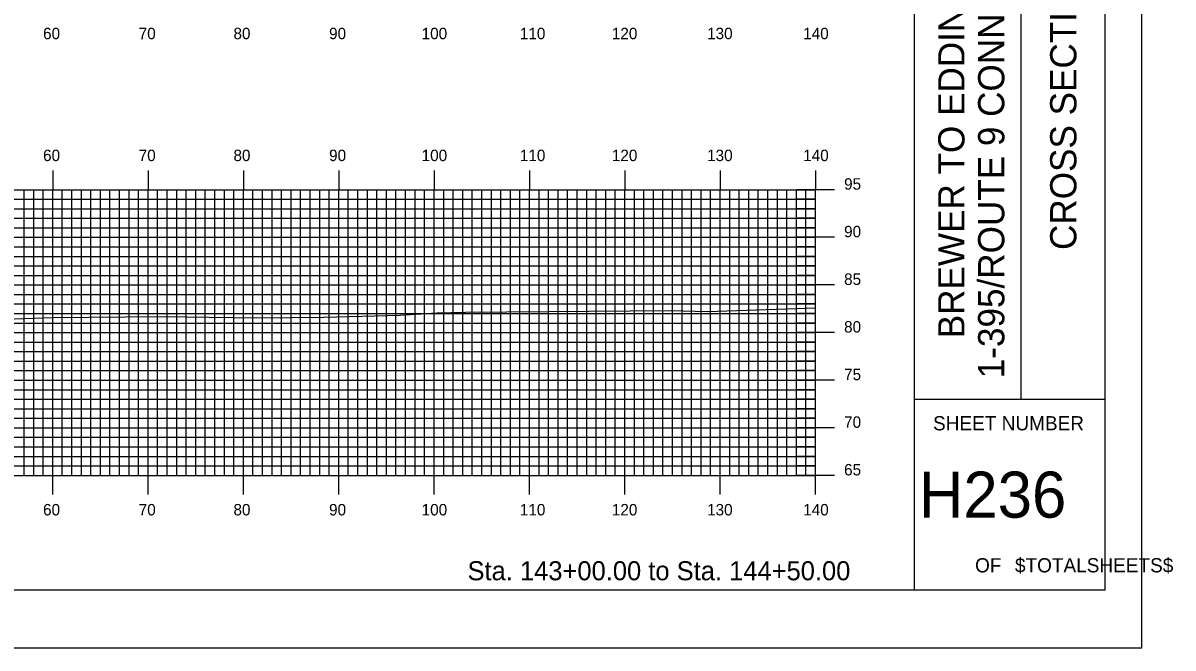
# Model space of a CAD drawing. Extents: x 1777138 to 1777481, y 442591 to 442811.
# Drawn here: x 1777360.6 to 1777481.3, y 442590.5 to 442656.2 of the extents above; entities that cross this region are included whole.
import ezdxf

# ---------------------------------------------------------------- set-up
doc = ezdxf.new("R2010")
doc.units = 0
for name, color, linetype in [('BORDER', 7, 'Continuous'), ('H_V ANNOTATION', 7, 'Continuous'), ('MAJOR', 7, 'Continuous'), ('MINOR', 7, 'Continuous'), ('PLOT BOUNDARY', 7, 'Continuous'), ('S_Roadway_Centerline', 7, 'Continuous')]:
    doc.layers.add(name, color=color, linetype=linetype)

msp = doc.modelspace()

# ---------------------------------------------------------------- linework, layer by layer
at = {"layer": 'BORDER'}
for p, q in [((1777454.16, 442596.67), (1777454.16, 442806.67)), ((1777465.35, 442616.67), (1777465.35, 442686.67)), ((1777454.16, 442616.67), (1777474.16, 442616.67))]:
    msp.add_line(p, q, dxfattribs=at)
msp.add_lwpolyline([(1777154.16, 442596.67), (1777474.16, 442596.67), (1777474.16, 442806.67), (1777154.16, 442806.67)], close=True, dxfattribs=at)
at = {"layer": 'MAJOR'}
for p, q in [((1777363.76, 442640.67), (1777363.76, 442638.67)), ((1777373.76, 442640.67), (1777373.76, 442638.67)), ((1777383.76, 442640.67), (1777383.76, 442638.67)), ((1777393.76, 442640.67), (1777393.76, 442638.67)), ((1777403.76, 442640.67), (1777403.76, 442638.67)), ((1777413.76, 442640.67), (1777413.76, 442638.67)), ((1777423.76, 442640.67), (1777423.76, 442638.67)), ((1777433.76, 442640.67), (1777433.76, 442638.67)), ((1777443.76, 442640.67), (1777443.76, 442638.67)), ((1777163.76, 442638.67), (1777443.76, 442638.67)), ((1777163.76, 442638.67), (1777443.76, 442638.67)), ((1777363.76, 442608.67), (1777363.76, 442638.67)), ((1777373.76, 442608.67), (1777373.76, 442638.67)), ((1777383.76, 442608.67), (1777383.76, 442638.67)), ((1777393.76, 442608.67), (1777393.76, 442638.67)), ((1777403.76, 442608.67), (1777403.76, 442638.67)), ((1777413.76, 442608.67), (1777413.76, 442638.67)), ((1777423.76, 442608.67), (1777423.76, 442638.67)), ((1777433.76, 442608.67), (1777433.76, 442638.67)), ((1777445.77, 442638.67), (1777441.76, 442638.67)), ((1777443.76, 442608.67), (1777443.76, 442638.67)), ((1777443.76, 442608.67), (1777443.76, 442638.67)), ((1777163.76, 442633.67), (1777443.76, 442633.67)), ((1777445.77, 442633.67), (1777441.76, 442633.67)), ((1777163.76, 442628.67), (1777443.76, 442628.67)), ((1777445.77, 442628.67), (1777441.76, 442628.67)), ((1777163.76, 442623.67), (1777443.76, 442623.67)), ((1777445.77, 442623.67), (1777441.76, 442623.67)), ((1777163.76, 442618.67), (1777443.76, 442618.67)), ((1777445.77, 442618.67), (1777441.76, 442618.67)), ((1777163.76, 442613.67), (1777443.76, 442613.67)), ((1777445.77, 442613.67), (1777441.76, 442613.67)), ((1777163.76, 442608.67), (1777443.76, 442608.67)), ((1777163.76, 442608.67), (1777443.76, 442608.67)), ((1777363.76, 442606.66), (1777363.76, 442608.67)), ((1777373.76, 442606.66), (1777373.76, 442608.67)), ((1777383.76, 442606.66), (1777383.76, 442608.67)), ((1777393.76, 442606.66), (1777393.76, 442608.67)), ((1777403.76, 442606.66), (1777403.76, 442608.67)), ((1777413.76, 442606.66), (1777413.76, 442608.67)), ((1777423.76, 442606.66), (1777423.76, 442608.67)), ((1777433.76, 442606.66), (1777433.76, 442608.67)), ((1777445.77, 442608.67), (1777441.76, 442608.67)), ((1777443.76, 442606.66), (1777443.76, 442608.67))]:
    msp.add_line(p, q, dxfattribs=at)
at = {"layer": 'MINOR'}
for p, q in [((1777163.76, 442637.67), (1777443.76, 442637.67)), ((1777360.76, 442608.67), (1777360.76, 442638.67)), ((1777361.76, 442608.67), (1777361.76, 442638.67)), ((1777362.76, 442608.67), (1777362.76, 442638.67)), ((1777364.76, 442608.67), (1777364.76, 442638.67)), ((1777365.76, 442608.67), (1777365.76, 442638.67)), ((1777366.76, 442608.67), (1777366.76, 442638.67)), ((1777367.76, 442608.67), (1777367.76, 442638.67)), ((1777368.76, 442608.67), (1777368.76, 442638.67)), ((1777369.76, 442608.67), (1777369.76, 442638.67)), ((1777370.76, 442608.67), (1777370.76, 442638.67)), ((1777371.76, 442608.67), (1777371.76, 442638.67)), ((1777372.76, 442608.67), (1777372.76, 442638.67)), ((1777374.76, 442608.67), (1777374.76, 442638.67)), ((1777375.76, 442608.67), (1777375.76, 442638.67)), ((1777376.76, 442608.67), (1777376.76, 442638.67)), ((1777377.76, 442608.67), (1777377.76, 442638.67)), ((1777378.76, 442608.67), (1777378.76, 442638.67)), ((1777379.76, 442608.67), (1777379.76, 442638.67)), ((1777380.76, 442608.67), (1777380.76, 442638.67)), ((1777381.76, 442608.67), (1777381.76, 442638.67)), ((1777382.76, 442608.67), (1777382.76, 442638.67)), ((1777384.76, 442608.67), (1777384.76, 442638.67)), ((1777385.76, 442608.67), (1777385.76, 442638.67)), ((1777386.76, 442608.67), (1777386.76, 442638.67)), ((1777387.76, 442608.67), (1777387.76, 442638.67)), ((1777388.76, 442608.67), (1777388.76, 442638.67)), ((1777389.76, 442608.67), (1777389.76, 442638.67)), ((1777390.76, 442608.67), (1777390.76, 442638.67)), ((1777391.76, 442608.67), (1777391.76, 442638.67)), ((1777392.76, 442608.67), (1777392.76, 442638.67)), ((1777394.76, 442608.67), (1777394.76, 442638.67)), ((1777395.76, 442608.67), (1777395.76, 442638.67)), ((1777396.76, 442608.67), (1777396.76, 442638.67)), ((1777397.76, 442608.67), (1777397.76, 442638.67)), ((1777398.76, 442608.67), (1777398.76, 442638.67)), ((1777399.76, 442608.67), (1777399.76, 442638.67)), ((1777400.76, 442608.67), (1777400.76, 442638.67)), ((1777401.76, 442608.67), (1777401.76, 442638.67)), ((1777402.76, 442608.67), (1777402.76, 442638.67)), ((1777404.76, 442608.67), (1777404.76, 442638.67)), ((1777405.76, 442608.67), (1777405.76, 442638.67)), ((1777406.76, 442608.67), (1777406.76, 442638.67)), ((1777407.76, 442608.67), (1777407.76, 442638.67)), ((1777408.76, 442608.67), (1777408.76, 442638.67)), ((1777409.76, 442608.67), (1777409.76, 442638.67)), ((1777410.76, 442608.67), (1777410.76, 442638.67)), ((1777411.76, 442608.67), (1777411.76, 442638.67)), ((1777412.76, 442608.67), (1777412.76, 442638.67)), ((1777414.76, 442608.67), (1777414.76, 442638.67)), ((1777415.76, 442608.67), (1777415.76, 442638.67)), ((1777416.76, 442608.67), (1777416.76, 442638.67)), ((1777417.76, 442608.67), (1777417.76, 442638.67)), ((1777418.76, 442608.67), (1777418.76, 442638.67)), ((1777419.76, 442608.67), (1777419.76, 442638.67)), ((1777420.76, 442608.67), (1777420.76, 442638.67)), ((1777421.76, 442608.67), (1777421.76, 442638.67)), ((1777422.76, 442608.67), (1777422.76, 442638.67)), ((1777424.76, 442608.67), (1777424.76, 442638.67)), ((1777425.76, 442608.67), (1777425.76, 442638.67)), ((1777426.76, 442608.67), (1777426.76, 442638.67)), ((1777427.76, 442608.67), (1777427.76, 442638.67)), ((1777428.76, 442608.67), (1777428.76, 442638.67)), ((1777429.76, 442608.67), (1777429.76, 442638.67)), ((1777430.76, 442608.67), (1777430.76, 442638.67)), ((1777431.76, 442608.67), (1777431.76, 442638.67)), ((1777432.76, 442608.67), (1777432.76, 442638.67)), ((1777434.76, 442608.67), (1777434.76, 442638.67)), ((1777435.76, 442608.67), (1777435.76, 442638.67)), ((1777436.76, 442608.67), (1777436.76, 442638.67)), ((1777437.76, 442608.67), (1777437.76, 442638.67)), ((1777438.76, 442608.67), (1777438.76, 442638.67)), ((1777439.76, 442608.67), (1777439.76, 442638.67)), ((1777440.76, 442608.67), (1777440.76, 442638.67)), ((1777441.76, 442608.67), (1777441.76, 442638.67)), ((1777443.76, 442637.67), (1777441.76, 442637.67)), ((1777442.76, 442608.67), (1777442.76, 442638.67)), ((1777163.76, 442636.67), (1777443.76, 442636.67)), ((1777443.76, 442636.67), (1777441.76, 442636.67)), ((1777163.76, 442635.67), (1777443.76, 442635.67)), ((1777443.76, 442635.67), (1777441.76, 442635.67)), ((1777163.76, 442634.67), (1777443.76, 442634.67)), ((1777443.76, 442634.67), (1777441.76, 442634.67)), ((1777163.76, 442632.67), (1777443.76, 442632.67)), ((1777163.76, 442631.67), (1777443.76, 442631.67)), ((1777443.76, 442632.67), (1777441.76, 442632.67)), ((1777443.76, 442631.67), (1777441.76, 442631.67)), ((1777163.76, 442630.67), (1777443.76, 442630.67)), ((1777443.76, 442630.67), (1777441.76, 442630.67)), ((1777163.76, 442629.67), (1777443.76, 442629.67)), ((1777443.76, 442629.67), (1777441.76, 442629.67)), ((1777163.76, 442627.67), (1777443.76, 442627.67)), ((1777443.76, 442627.67), (1777441.76, 442627.67)), ((1777163.76, 442626.67), (1777443.76, 442626.67)), ((1777163.76, 442625.67), (1777443.76, 442625.67)), ((1777443.76, 442626.67), (1777441.76, 442626.67)), ((1777443.76, 442625.67), (1777441.76, 442625.67)), ((1777163.76, 442624.67), (1777443.76, 442624.67)), ((1777443.76, 442624.67), (1777441.76, 442624.67)), ((1777163.76, 442622.67), (1777443.76, 442622.67)), ((1777443.76, 442622.67), (1777441.76, 442622.67)), ((1777163.76, 442621.67), (1777443.76, 442621.67)), ((1777443.76, 442621.67), (1777441.76, 442621.67)), ((1777163.76, 442620.67), (1777443.76, 442620.67)), ((1777163.76, 442619.67), (1777443.76, 442619.67)), ((1777443.76, 442620.67), (1777441.76, 442620.67)), ((1777443.76, 442619.67), (1777441.76, 442619.67)), ((1777163.76, 442617.67), (1777443.76, 442617.67)), ((1777443.76, 442617.67), (1777441.76, 442617.67)), ((1777163.76, 442616.67), (1777443.76, 442616.67)), ((1777443.76, 442616.67), (1777441.76, 442616.67)), ((1777163.76, 442615.67), (1777443.76, 442615.67)), ((1777443.76, 442615.67), (1777441.76, 442615.67)), ((1777163.76, 442614.67), (1777443.76, 442614.67)), ((1777443.76, 442614.67), (1777441.76, 442614.67)), ((1777163.76, 442612.67), (1777443.76, 442612.67)), ((1777443.76, 442612.67), (1777441.76, 442612.67)), ((1777163.76, 442611.67), (1777443.76, 442611.67)), ((1777443.76, 442611.67), (1777441.76, 442611.67)), ((1777163.76, 442610.67), (1777443.76, 442610.67)), ((1777443.76, 442610.67), (1777441.76, 442610.67)), ((1777163.76, 442609.67), (1777443.76, 442609.67)), ((1777443.76, 442609.67), (1777441.76, 442609.67))]:
    msp.add_line(p, q, dxfattribs=at)
at = {"layer": 'PLOT BOUNDARY'}
msp.add_lwpolyline([(1777137.98, 442590.55), (1777477.98, 442590.55), (1777477.98, 442810.55), (1777137.98, 442810.55)], close=True, dxfattribs=at)
at = {"layer": 'S_Roadway_Centerline'}
msp.add_lwpolyline([(1777357.72, 442625.05), (1777363.74, 442625.26), (1777375.21, 442625.35), (1777385.13, 442625.21), (1777392.19, 442625.28), (1777400.2, 442625.51), (1777404.06, 442625.73), (1777407.04, 442625.8), (1777428.63, 442625.97), (1777432.41, 442625.87), (1777443.76, 442626.26)], dxfattribs=at)

# ---------------------------------------------------------------- texts
at = {"layer": 'BORDER'}
for s, p in [('1-395/ROUTE 9 CONNECTOR', (1777463.57, 442618.87)), ('BREWER TO EDDINGTON', (1777459.39, 442623.07)), ('CROSS SECTIONS', (1777471.13, 442632.34))]:
    msp.add_text(s, height=2.7557, rotation=90, dxfattribs=at).set_placement(p)
for s, height, p in [('SHEET NUMBER', 1.4905, (1777456.09, 442613.4)), ('H236', 4.839, (1777454.6, 442604.23)), ('OF', 1.491, (1777460.5, 442598.49)), ('$TOTALSHEETS$', 1.4905, (1777464.68, 442598.49))]:
    msp.add_text(s, height=height, dxfattribs=at).set_placement(p)
at = {"layer": 'H_V ANNOTATION'}
for s, height, p in [('60', 1.2, (1777362.74, 442654.47)), ('70', 1.2, (1777372.77, 442654.47)), ('80', 1.2, (1777382.71, 442654.47)), ('90', 1.2, (1777392.74, 442654.47)), ('100', 1.2, (1777402.45, 442654.47)), ('110', 1.2, (1777412.75, 442654.47)), ('120', 1.2, (1777422.4, 442654.47)), ('130', 1.2, (1777432.39, 442654.47)), ('140', 1.2, (1777442.47, 442654.47)), ('60', 1.2, (1777362.74, 442641.67)), ('70', 1.2, (1777372.77, 442641.67)), ('80', 1.2, (1777382.71, 442641.67)), ('90', 1.2, (1777392.74, 442641.67)), ('100', 1.2, (1777402.45, 442641.67)), ('110', 1.2, (1777412.75, 442641.67)), ('120', 1.2, (1777422.4, 442641.67)), ('130', 1.2, (1777432.39, 442641.67)), ('140', 1.2, (1777442.47, 442641.67)), ('95', 1.2, (1777446.76, 442638.67)), ('90', 1.2, (1777446.76, 442633.67)), ('85', 1.2, (1777446.76, 442628.67)), ('80', 1.2, (1777446.76, 442623.67)), ('75', 1.2, (1777446.76, 442618.67)), ('70', 1.2, (1777446.76, 442613.67)), ('65', 1.2, (1777446.76, 442608.67)), ('60', 1.2, (1777362.74, 442604.47)), ('70', 1.2, (1777372.77, 442604.47)), ('80', 1.2, (1777382.71, 442604.47)), ('90', 1.2, (1777392.74, 442604.47)), ('100', 1.2, (1777402.45, 442604.47)), ('110', 1.2, (1777412.75, 442604.47)), ('120', 1.2, (1777422.4, 442604.47)), ('130', 1.2, (1777432.39, 442604.47)), ('140', 1.2, (1777442.47, 442604.47)), ('Sta. 143+00.00 to Sta. 144+50.00', 2.0004, (1777407.26, 442597.66))]:
    msp.add_text(s, height=height, dxfattribs=at).set_placement(p)

doc.saveas('drawing.dxf')
